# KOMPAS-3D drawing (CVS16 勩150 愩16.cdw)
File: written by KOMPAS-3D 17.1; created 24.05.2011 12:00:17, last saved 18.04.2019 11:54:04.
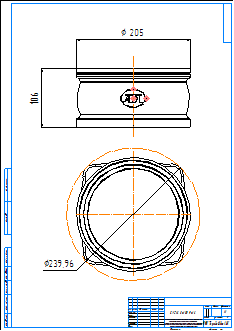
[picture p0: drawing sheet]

Title block, sheet 1: name: CVS16 Ду150 Ру16; material: Внимание! Данный продукт является объектом авторского права ООО «Торговый Дом АДЛ». / Запрещается изменение, копирование, распространение / (в том числе путем копирования на другие сайты и ресурсы в Интернете) / или любое иное использование информации и объектов без предварительного / согласия правообладателя (ООО «Торговый Дом АДЛ»).; scale: 1:1; sheets: 1; organisation: ООО "Торговый дом АДЛ"; sheet format: A2; stored path: \\adlc.lan\data\АДЛ_ПКД\3D-модели\ADL production\Клапаны обратные ГРАНЛОК\CVS16\KOMPAS 2D\CVS16 Ду150 Ру16.cdw

Views: Спереди 1, Проекционный вид 2
Dimensions and other numbers on the sheet: 106; 205; 239,96; 1:1; 1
